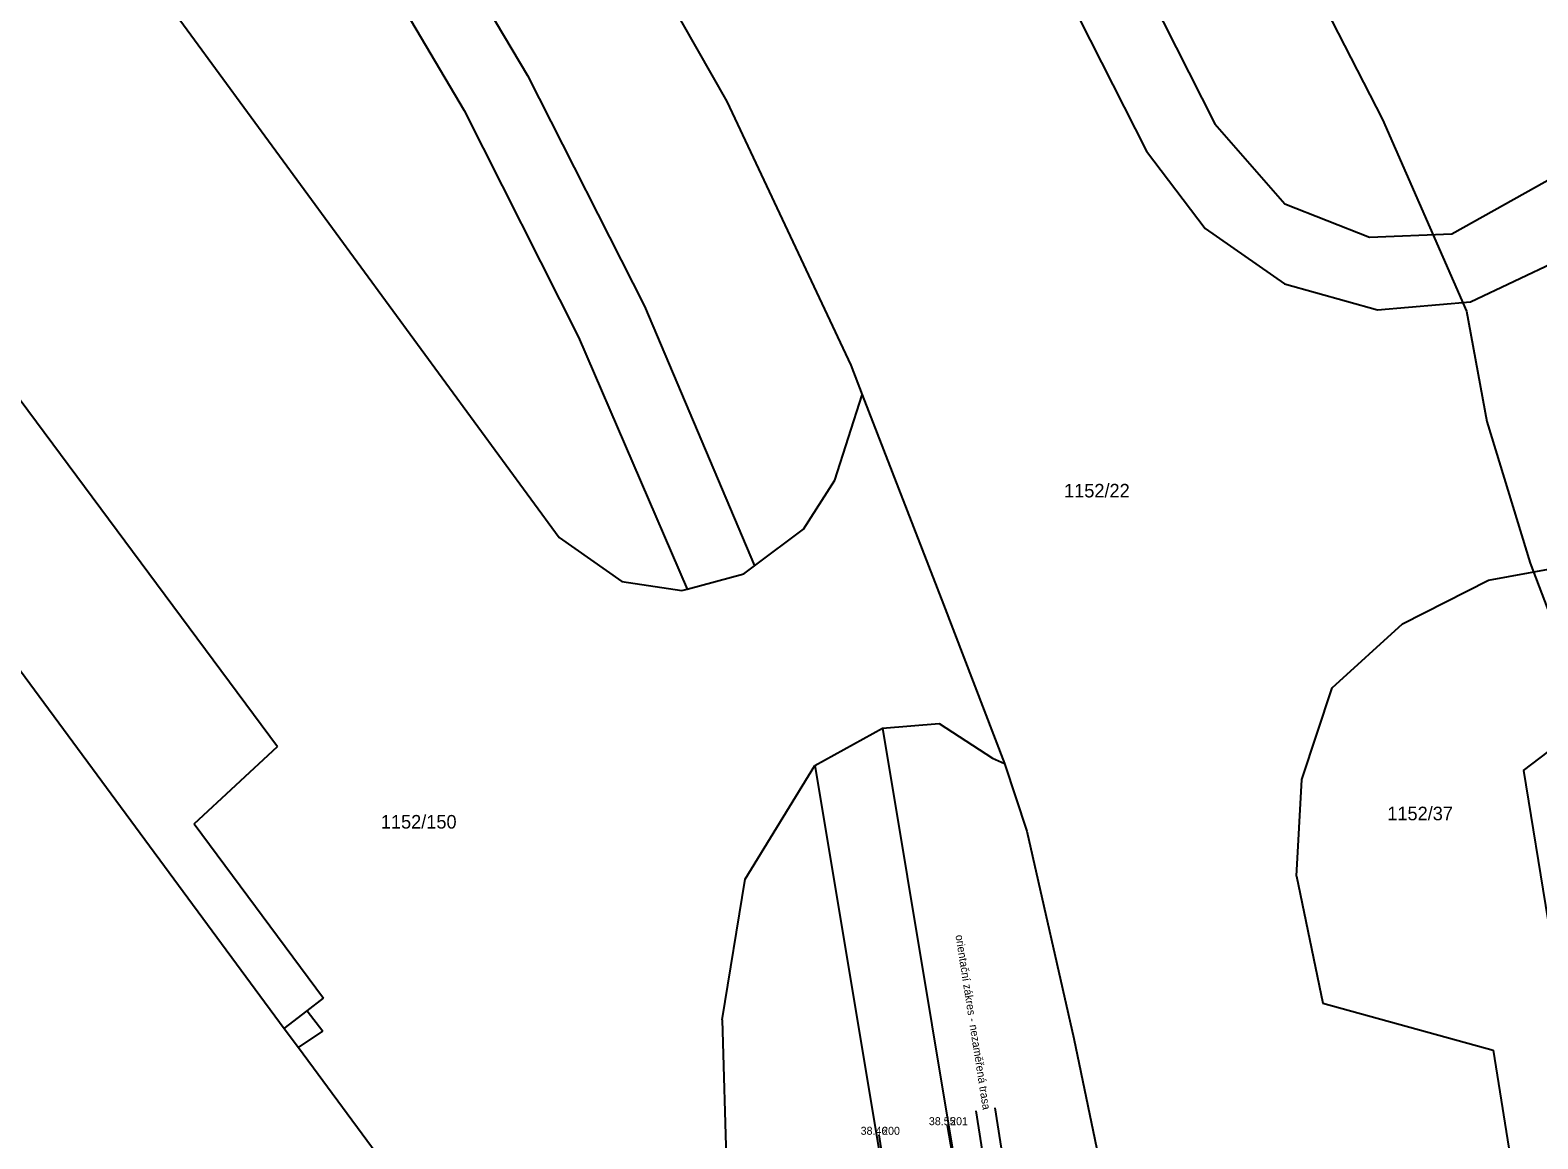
# Model space of a CAD drawing. Extents: x -609709 to -609357, y -1051535 to -1051131.
# Drawn here: x -609544.11 to -609496.91, y -1051262.77 to -1051228.08 of the extents above; entities that cross this region are included whole.
import ezdxf

# ---------------------------------------------------------------- set-up
doc = ezdxf.new("R2010")
doc.units = 0
for name, color, linetype in [('Vrstva 1', 7, 'Continuous'), ('Vrstva 10', 7, 'Continuous'), ('Vrstva 15', 7, 'Continuous'), ('Vrstva 19', 7, 'Continuous'), ('Vrstva 2', 7, 'Continuous'), ('Vrstva 3', 7, 'Continuous'), ('Vrstva 4', 7, 'Continuous')]:
    doc.layers.add(name, color=color, linetype=linetype)

msp = doc.modelspace()

# ---------------------------------------------------------------- linework, layer by layer
at = {"layer": 'Vrstva 1'}
for p, q in [((-609517.53, -1051262.64), (-609517.53, -1051262.64)), ((-609515.4, -1051262.34), (-609515.4, -1051262.34))]:
    msp.add_line(p, q, dxfattribs=at)
at = {"layer": 'Vrstva 10'}
for p, q in [((-609517.84, -1051214.72), (-609509.16, -1051231.87)), ((-609514.29, -1051216.67), (-609507.02, -1051231.01)), ((-609535.06, -1051218.45), (-609528.54, -1051229.5)), ((-609537.03, -1051219.62), (-609530.52, -1051230.59)), ((-609527.31, -1051221.49), (-609522.3, -1051230.31)), ((-609542.5, -1051223.56), (-609527.55, -1051243.95)), ((-609528.54, -1051229.5), (-609524.88, -1051236.72)), ((-609551.24, -1051230.48), (-609536.37, -1051250.49)), ((-609530.52, -1051230.59), (-609526.94, -1051237.68)), ((-609522.3, -1051230.31), (-609518.42, -1051238.56)), ((-609507.02, -1051231.01), (-609504.83, -1051233.51)), ((-609509.16, -1051231.87), (-609507.32, -1051234.28)), ((-609499.6, -1051234.45), (-609496.33, -1051232.63)), ((-609504.83, -1051233.51), (-609502.18, -1051234.56)), ((-609507.32, -1051234.28), (-609504.84, -1051236.02)), ((-609554.21, -1051234.86), (-609536.16, -1051259.31)), ((-609502.18, -1051234.56), (-609499.6, -1051234.45)), ((-609499.02, -1051236.58), (-609496.28, -1051235.29)), ((-609504.84, -1051236.02), (-609501.93, -1051236.83)), ((-609524.88, -1051236.72), (-609521.43, -1051244.84)), ((-609501.93, -1051236.83), (-609499.02, -1051236.58)), ((-609526.94, -1051237.68), (-609523.54, -1051245.57)), ((-609518.42, -1051238.56), (-609518.06, -1051239.49)), ((-609518.92, -1051242.16), (-609518.06, -1051239.49)), ((-609518.06, -1051239.49), (-609515.52, -1051246.05)), ((-609519.9, -1051243.69), (-609518.92, -1051242.16)), ((-609521.43, -1051244.84), (-609519.9, -1051243.69)), ((-609527.55, -1051243.95), (-609525.59, -1051245.33)), ((-609498.45, -1051245.29), (-609495.48, -1051244.74)), ((-609523.54, -1051245.57), (-609521.77, -1051245.09)), ((-609521.77, -1051245.09), (-609521.43, -1051244.84)), ((-609525.59, -1051245.33), (-609523.71, -1051245.61)), ((-609523.71, -1051245.61), (-609523.54, -1051245.57)), ((-609501.14, -1051246.65), (-609498.45, -1051245.29)), ((-609515.52, -1051246.05), (-609513.61, -1051251.02)), ((-609503.35, -1051248.66), (-609501.14, -1051246.65)), ((-609504.3, -1051251.52), (-609503.35, -1051248.66)), ((-609519.54, -1051251.09), (-609517.43, -1051249.92)), ((-609517.43, -1051249.92), (-609515.65, -1051249.77)), ((-609517.43, -1051249.92), (-609506.51, -1051315.51)), ((-609515.65, -1051249.77), (-609513.98, -1051250.86)), ((-609497.36, -1051251.24), (-609495.18, -1051249.58)), ((-609538.97, -1051252.91), (-609536.37, -1051250.49)), ((-609513.98, -1051250.86), (-609513.61, -1051251.02)), ((-609521.72, -1051254.64), (-609519.54, -1051251.09)), ((-609519.54, -1051251.09), (-609508.96, -1051314.48)), ((-609513.61, -1051251.02), (-609512.91, -1051253.14)), ((-609497.36, -1051251.24), (-609489.75, -1051298)), ((-609504.46, -1051254.55), (-609504.3, -1051251.52)), ((-609538.97, -1051252.91), (-609534.93, -1051258.37)), ((-609512.91, -1051253.14), (-609511.43, -1051259.63)), ((-609522.44, -1051259.04), (-609521.72, -1051254.64)), ((-609504.46, -1051254.55), (-609503.64, -1051258.52)), ((-609535.44, -1051258.76), (-609534.93, -1051258.37)), ((-609536.16, -1051259.31), (-609535.44, -1051258.76)), ((-609535.44, -1051258.76), (-609534.95, -1051259.4)), ((-609503.64, -1051258.52), (-609498.31, -1051259.99)), ((-609536.16, -1051259.31), (-609535.71, -1051259.91)), ((-609535.71, -1051259.91), (-609534.95, -1051259.4)), ((-609522.44, -1051259.04), (-609522.31, -1051263.72)), ((-609535.71, -1051259.91), (-609530.16, -1051267.42)), ((-609511.43, -1051259.63), (-609508.34, -1051274.51)), ((-609498.31, -1051259.99), (-609492.16, -1051298.11))]:
    msp.add_line(p, q, dxfattribs=at)
at = {"layer": 'Vrstva 15'}
msp.add_lwpolyline([(-609521.08, -1051202.07), (-609519.34, -1051204.67), (-609514.81, -1051210.66), (-609514.03, -1051211.19), (-609512.3, -1051214.35), (-609507.99, -1051219.96), (-609504.74, -1051225.1), (-609501.77, -1051230.87), (-609499.14, -1051236.87), (-609498.5, -1051240.32), (-609497.15, -1051244.76), (-609494.99, -1051250.43), (-609489.96, -1051247.93), (-609488.37, -1051245.86), (-609482.36, -1051244.46), (-609480.27, -1051243.11), (-609478.75, -1051243.5), (-609475.39, -1051242.82), (-609472.143, -1051242.924)], dxfattribs=at)
at = {"layer": 'Vrstva 19'}
for points in [[(-609513.91, -1051261.8), (-609509.35, -1051290.83), (-609510.76, -1051291.051), (-609510.504, -1051292.681), (-609509.17, -1051292.471), (-609503.272, -1051330.02)], [(-609514.503, -1051261.893), (-609510.036, -1051290.33), (-609511.446, -1051290.552), (-609511.003, -1051293.366), (-609509.669, -1051293.157), (-609503.864, -1051330.113)]]:
    msp.add_lwpolyline(points, dxfattribs=at)
at = {"layer": 'Vrstva 4'}
for points in [[(-609512.72, -1051291.73), (-609513.15, -1051289.31), (-609513.66, -1051285.85), (-609514.29, -1051281.88), (-609514.93, -1051278.33), (-609515.9, -1051272.74), (-609516.8, -1051267.39), (-609517.53, -1051262.64)], [(-609515.4, -1051262.34), (-609514.53, -1051267.36), (-609513.69, -1051272.45), (-609512.77, -1051277.93), (-609512.21, -1051281.29), (-609511.39, -1051285.79), (-609510.95, -1051289.01), (-609510.16, -1051293.31), (-609512.29, -1051293.69), (-609512.72, -1051291.73)]]:
    msp.add_lwpolyline(points, dxfattribs=at)

# ---------------------------------------------------------------- texts
at = {"layer": 'Vrstva 10'}
for s, p in [('1152/22', (-609511.74, -1051242.7)), ('1152/37', (-609501.62, -1051252.8)), ('1152/150', (-609533.13, -1051253.06))]:
    msp.add_text(s, height=0.425, dxfattribs=at).set_placement(p)
at = {"layer": 'Vrstva 19'}
msp.add_text('orientační zákres - nezaměřená trasa', height=0.25, rotation=278.927, dxfattribs=at).set_placement((-609515.141, -1051256.401))
at = {"layer": 'Vrstva 2'}
for s, p in [(' 201', (-609515.4, -1051262.34)), (' 200', (-609517.53, -1051262.64))]:
    msp.add_text(s, height=0.25, dxfattribs=at).set_placement(p)
at = {"layer": 'Vrstva 3'}
for s, p in [('38.55', (-609515.973, -1051262.34)), ('38.46', (-609518.109, -1051262.64))]:
    msp.add_text(s, height=0.25, dxfattribs=at).set_placement(p)

doc.saveas('drawing.dxf')
